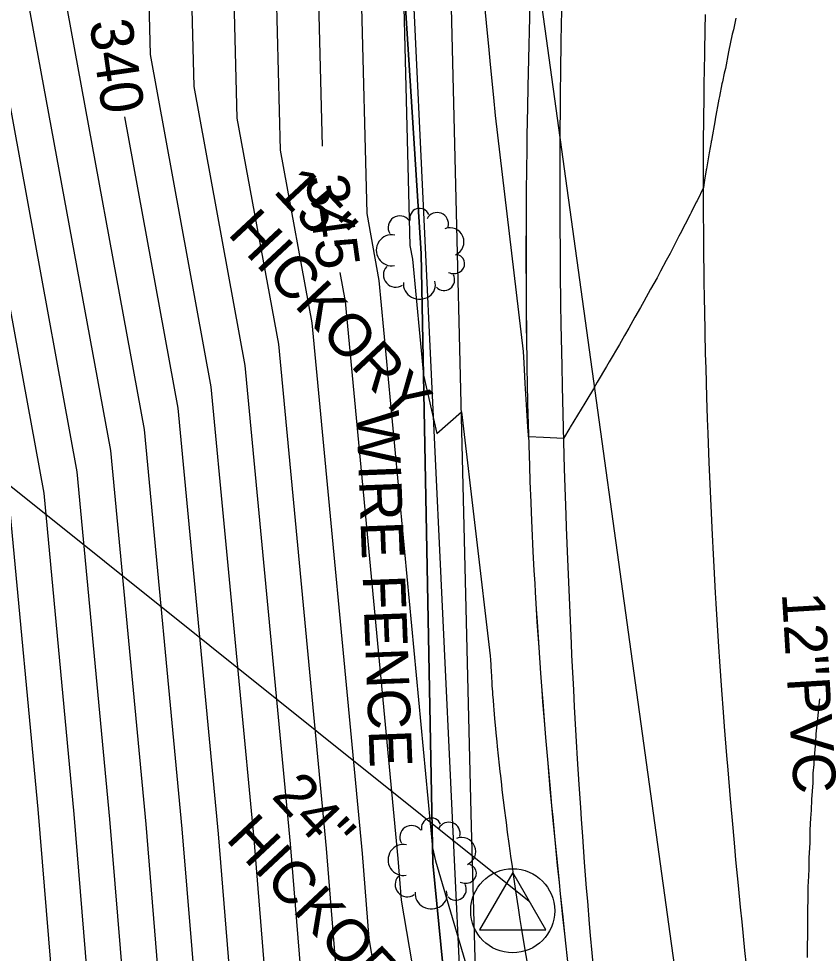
# Model space of a CAD drawing. Extents: x 487096 to 489566, y 221939 to 224454.
# Drawn here: x 488356.5 to 488416.7, y 222911.5 to 222981.8 of the extents above; entities that cross this region are included whole.
import ezdxf

# ---------------------------------------------------------------- set-up
doc = ezdxf.new("R2010")
doc.units = 0
for name, color, linetype in [('SV_BKLN_EARTH_TOP', 7, 'Continuous'), ('SV_CTRL_BM_INFO_BOX', 7, 'Continuous'), ('SV_CTRL_CGS', 7, 'Continuous'), ('SV_FENC_FENCES', 7, 'Continuous'), ('SV_FENC_FENCES_TX', 7, 'Continuous'), ('SV_MISC_MISC_TOPO', 7, 'Continuous'), ('SV_PIPE_PLAS_TX', 7, 'Continuous'), ('SV_ROAD_BITRD', 7, 'Continuous'), ('SV_ROWL_HWYLOC', 7, 'Continuous'), ('SV_SURF_INDEX_CONTOUR', 7, 'Continuous'), ('SV_SURF_INTER_CONTOUR', 7, 'Continuous'), ('SV_TRAF_PVMTL', 7, 'Continuous'), ('SV_TREE_TREEVEG', 7, 'Continuous'), ('SV_TREE_TREEVEG_TX', 7, 'Continuous'), ('SV_UTOH_OVERHEAD_LINES', 7, 'Continuous')]:
    doc.layers.add(name, color=color, linetype=linetype)

msp = doc.modelspace()

# ---------------------------------------------------------------- linework, layer by layer
at = {"layer": 'SV_BKLN_EARTH_TOP'}
msp.add_lwpolyline([(488391.814, 222875.894), (488390.567, 222921.008), (488388.639, 223000.073), (488389.407, 223042.325), (488396.478, 223078.484), (488405.528, 223123.261), (488407.475, 223152.677)], dxfattribs=at)
at = {"layer": 'SV_CTRL_BM_INFO_BOX'}
msp.add_line((488260.98, 223022.493), (488394.91, 222915.382), dxfattribs=at)
at = {"layer": 'SV_CTRL_CGS'}
msp.add_line((488393.66, 222914.66), (488393.66, 222914.66), dxfattribs=at)
msp.add_line((488393.66, 222914.66), (488393.66, 222914.66), dxfattribs=at)
msp.add_line((488393.66, 222914.66), (488393.66, 222914.66), dxfattribs=at)
msp.add_line((488393.66, 222914.66), (488393.66, 222914.66), dxfattribs=at)
msp.add_line((488393.66, 222914.66), (488393.66, 222914.66), dxfattribs=at)
msp.add_line((488393.66, 222914.66), (488393.66, 222914.66), dxfattribs=at)
msp.add_line((488393.66, 222914.66), (488393.66, 222914.66), dxfattribs=at)
msp.add_line((488393.66, 222914.66), (488393.66, 222914.66), dxfattribs=at)
msp.add_line((488393.66, 222914.66), (488393.66, 222914.66), dxfattribs=at)
msp.add_lwpolyline([(488393.66, 222917.548), (488391.159, 222913.217), (488396.161, 222913.217)], close=True, dxfattribs=at)
msp.add_lwpolyline([(488393.66, 222917.548), (488391.159, 222913.217), (488396.161, 222913.217)], close=True, dxfattribs=at)
msp.add_lwpolyline([(488393.66, 222917.548), (488391.159, 222913.217), (488396.161, 222913.217)], close=True, dxfattribs=at)
msp.add_lwpolyline([(488393.66, 222917.548), (488391.159, 222913.217), (488396.161, 222913.217)], close=True, dxfattribs=at)
msp.add_lwpolyline([(488393.66, 222917.548), (488391.159, 222913.217), (488396.161, 222913.217)], close=True, dxfattribs=at)
msp.add_lwpolyline([(488393.66, 222917.548), (488391.159, 222913.217), (488396.161, 222913.217)], close=True, dxfattribs=at)
msp.add_lwpolyline([(488393.66, 222917.548), (488391.159, 222913.217), (488396.161, 222913.217)], close=True, dxfattribs=at)
msp.add_lwpolyline([(488393.66, 222917.548), (488391.159, 222913.217), (488396.161, 222913.217)], close=True, dxfattribs=at)
msp.add_lwpolyline([(488393.66, 222917.548), (488391.159, 222913.217), (488396.161, 222913.217)], close=True, dxfattribs=at)
msp.add_circle((488393.66, 222914.66), 3.161, dxfattribs=at)
msp.add_circle((488393.66, 222914.66), 3.161, dxfattribs=at)
msp.add_circle((488393.66, 222914.66), 3.161, dxfattribs=at)
msp.add_circle((488393.66, 222914.66), 3.161, dxfattribs=at)
msp.add_circle((488393.66, 222914.66), 3.161, dxfattribs=at)
msp.add_circle((488393.66, 222914.66), 3.161, dxfattribs=at)
msp.add_circle((488393.66, 222914.66), 3.161, dxfattribs=at)
msp.add_circle((488393.66, 222914.66), 3.161, dxfattribs=at)
msp.add_circle((488393.66, 222914.66), 3.161, dxfattribs=at)
at = {"layer": 'SV_FENC_FENCES'}
msp.add_lwpolyline([(488400.559, 222861.835), (488391.815, 222875.913), (488387.651, 222918.235), (488386.769, 222964.099), (488384.515, 222999.563), (488389.407, 223042.325), (488396.478, 223078.484), (488402.804, 223123.48), (488407.475, 223152.677), (488415.007, 223209.78), (488415.388, 223241.145)], dxfattribs=at)
at = {"layer": 'SV_MISC_MISC_TOPO'}
msp.add_line((488393.659, 222914.659), (488393.659, 222914.659), dxfattribs=at)
at = {"layer": 'SV_ROAD_BITRD'}
for points in [[(488394.95, 222982.911), (488394.894, 222980.827), (488394.868, 222979.784), (488394.819, 222977.7), (488394.797, 222976.657), (488394.767, 222975.094), (488394.732, 222973.009), (488394.717, 222971.967), (488394.698, 222970.404), (488394.682, 222968.84), (488394.676, 222968.058), (488394.664, 222965.974), (488394.661, 222964.932), (488394.661, 222963.369), (488394.665, 222961.806), (488394.668, 222961.024), (488394.679, 222959.461), (488394.687, 222958.68), (488394.7, 222957.508), (488394.72, 222956.119), (488394.731, 222955.424), (488394.75, 222954.383), (488394.783, 222952.821), (488394.821, 222951.259), (488394.843, 222950.478), (488394.89, 222948.916), (488394.916, 222948.135), (488394.957, 222946.964), (488395.018, 222945.403), (488395.05, 222944.623), (488395.102, 222943.452), (488395.187, 222941.697), (488395.263, 222940.248), (488395.316, 222939.282), (488395.353, 222938.638), (488395.431, 222937.35), (488395.492, 222936.385), (488395.62, 222934.454), (488395.757, 222932.524), (488395.853, 222931.237), (488395.919, 222930.379), (488396.056, 222928.665), (488396.136, 222927.7), (488396.3, 222925.771), (488396.472, 222923.843), (488396.59, 222922.558), (488396.671, 222921.702), (488396.835, 222919.989), (488397.026, 222918.062), (488397.156, 222916.778), (488397.244, 222915.922), (488397.423, 222914.21), (488397.56, 222912.927), (488397.84, 222910.36)], [(488394.951, 222982.911), (488394.895, 222980.827), (488394.869, 222979.784), (488394.82, 222977.7), (488394.799, 222976.658), (488394.768, 222975.094), (488394.734, 222973.01), (488394.719, 222971.967), (488394.699, 222970.404), (488394.684, 222968.84), (488394.678, 222968.059), (488394.666, 222965.974), (488394.664, 222964.932), (488394.663, 222963.369), (488394.667, 222961.806), (488394.671, 222961.024), (488394.682, 222959.462), (488394.689, 222958.68), (488394.702, 222957.508), (488394.722, 222956.119), (488394.733, 222955.425), (488394.752, 222954.383), (488394.785, 222952.821), (488394.823, 222951.259), (488394.845, 222950.478), (488394.891, 222948.916), (488394.917, 222948.136), (488394.958, 222946.965), (488395.018, 222945.403), (488395.051, 222944.623), (488395.102, 222943.452), (488395.187, 222941.697), (488395.262, 222940.248), (488395.316, 222939.282), (488395.353, 222938.638), (488395.43, 222937.35), (488395.49, 222936.385), (488395.618, 222934.454), (488395.754, 222932.523), (488395.85, 222931.237), (488395.915, 222930.379), (488396.052, 222928.664), (488396.131, 222927.699), (488396.295, 222925.771), (488396.466, 222923.843), (488396.584, 222922.557), (488396.664, 222921.701), (488396.829, 222919.988), (488397.019, 222918.061), (488397.149, 222916.777), (488397.238, 222915.921), (488397.417, 222914.209), (488397.554, 222912.926), (488397.835, 222910.359)], [(488394.951, 222982.911), (488394.895, 222980.827), (488394.869, 222979.784), (488394.82, 222977.7), (488394.799, 222976.658), (488394.768, 222975.094), (488394.734, 222973.01), (488394.719, 222971.967), (488394.699, 222970.404), (488394.684, 222968.84), (488394.678, 222968.059), (488394.666, 222965.974), (488394.664, 222964.932), (488394.663, 222963.369), (488394.667, 222961.806), (488394.671, 222961.024), (488394.682, 222959.462), (488394.689, 222958.68), (488394.702, 222957.508), (488394.722, 222956.119), (488394.733, 222955.425), (488394.752, 222954.383), (488394.785, 222952.821), (488394.823, 222951.259), (488394.845, 222950.478), (488394.891, 222948.916), (488394.917, 222948.136), (488394.958, 222946.965), (488395.018, 222945.403), (488395.051, 222944.623), (488395.102, 222943.452), (488395.187, 222941.697), (488395.262, 222940.248), (488395.316, 222939.282), (488395.353, 222938.638), (488395.43, 222937.35), (488395.49, 222936.385), (488395.618, 222934.454), (488395.754, 222932.523), (488395.85, 222931.237), (488395.915, 222930.379), (488396.052, 222928.664), (488396.131, 222927.699), (488396.295, 222925.771), (488396.466, 222923.843), (488396.584, 222922.557), (488396.664, 222921.701), (488396.829, 222919.988), (488397.019, 222918.061), (488397.149, 222916.777), (488397.238, 222915.921), (488397.417, 222914.209), (488397.554, 222912.926), (488397.835, 222910.359)]]:
    msp.add_lwpolyline(points, dxfattribs=at)
at = {"layer": 'SV_ROWL_HWYLOC'}
msp.add_lwpolyline([(488415.388, 223241.145), (488415.007, 223209.78), (488407.475, 223152.677), (488402.804, 223123.48), (488396.478, 223078.484), (488389.407, 223042.325), (488386.961, 223020.944), (488384.515, 222999.563), (488386.769, 222964.099), (488387.651, 222918.235), (488391.815, 222875.913), (488394, 222859.238), (488415.207, 222774.386)], dxfattribs=at)
at = {"layer": 'SV_SURF_INDEX_CONTOUR'}
for points in [[(488379.351, 222972.188), (488378.624, 223000.814), (488378.664, 223008.462), (488377.682, 223042.865), (488378.243, 223058.541)], [(488349.178, 222980.783), (488355.841, 222944.471), (488357.935, 222922.292), (488360.157, 222895.18)], [(488364.437, 222974.386), (488368.457, 222952.478), (488371.483, 222920.442), (488373.074, 222901.024), (488375.167, 222888.746)], [(488391.924, 222877.1), (488391.755, 222878.086), (488391.753, 222878.109), (488391.517, 222878.914), (488385.288, 222915.445), (488385.03, 222918.592), (488381.074, 222960.484), (488380.671, 222962.679)]]:
    msp.add_lwpolyline(points, dxfattribs=at)
at = {"layer": 'SV_SURF_INTER_CONTOUR'}
for points in [[(488330.362, 223253.848), (488333.719, 223206.864), (488336.408, 223199.126), (488339.342, 223176.141), (488341.304, 223168.886), (488341.3, 223168.777), (488341.297, 223168.703), (488341.254, 223167.912), (488342.109, 223162.381), (488351.687, 223120.879), (488344.088, 223092.286), (488344.066, 223086.717), (488348.882, 223046.653), (488349.877, 223039.173), (488349.711, 223006.955), (488350.116, 222991.025), (488358.364, 222946.073), (488360.645, 222921.922), (488363.302, 222889.487), (488365.53, 222876.424), (488366.64, 222870.732), (488367.437, 222866.835), (488368.962, 222859.132)], [(488372.119, 222858.013), (488370.811, 222864.614), (488369.835, 222869.39), (488368.475, 222876.365), (488365.745, 222892.371), (488363.354, 222921.552), (488360.887, 222947.674), (488353.372, 222988.633), (488352.924, 223006.273), (488353.107, 223041.947), (488352.698, 223045.029), (488348.943, 223076.261), (488347.531, 223089.211), (488348.287, 223091.807), (488355.921, 223120.534), (488348.771, 223151.516), (488346.419, 223166.724), (488346.539, 223168.899), (488346.547, 223169.1), (488346.559, 223169.401), (488341.163, 223189.349), (488339.561, 223201.893), (488338.094, 223206.116), (488336.262, 223231.758)], [(488384.744, 222853.534), (488384.309, 222855.733), (488382.615, 222864.021), (488380.254, 222876.127), (488375.517, 222903.908), (488374.192, 222920.072), (488370.98, 222954.079), (488366.396, 222979.065), (488365.774, 223003.544)], [(488368.987, 223002.861), (488369.652, 222976.673), (488373.504, 222955.68), (488376.902, 222919.702), (488377.959, 222906.792), (488383.199, 222876.068), (488385.81, 222862.679), (488387.683, 222853.512), (488387.901, 222852.415)], [(488372.199, 223002.179), (488372.908, 222974.281), (488376.027, 222957.282), (488379.611, 222919.332), (488380.402, 222909.677), (488386.143, 222876.008), (488389.005, 222861.336), (488391.053, 222851.316), (488391.058, 222851.3), (488391.061, 222851.295), (488391.069, 222851.269), (488391.073, 222851.259)], [(488375.412, 223001.496), (488376.164, 222971.889), (488378.55, 222958.883), (488382.32, 222918.962), (488382.845, 222912.561), (488389.088, 222875.949), (488392.2, 222859.994), (488392.938, 222856.383), (488394.511, 222851.739), (488395.558, 222850.018), (488395.793, 222849.216), (488396.036, 222848.395), (488396.287, 222847.555), (488396.547, 222846.693), (488396.815, 222845.811), (488397.093, 222844.906), (488397.379, 222843.979), (488397.676, 222843.027), (488397.983, 222842.051), (488398.301, 222841.048), (488398.629, 222840.019), (488398.969, 222838.962)], [(488381.837, 223000.132), (488382.676, 222967.106), (488383.597, 222962.086), (488387.628, 222919.4), (488387.853, 222918.427), (488390.928, 222907.928)], [(488375.275, 222856.893), (488374.185, 222862.394), (488373.03, 222868.047), (488371.419, 222876.305), (488368.188, 222895.256), (488366.064, 222921.182), (488363.411, 222949.275), (488356.628, 222986.241)], [(488385.401, 222985.627), (488385.932, 222964.714), (488386.12, 222963.687), (488386.945, 222954.956), (488387.962, 222950.561), (488389.806, 222952.199), (488391.971, 222933.849), (488391.986, 222933.543), (488392.005, 222933.173), (488392.016, 222932.985), (488392.032, 222932.7), (488392.058, 222932.264), (488392.087, 222931.818), (488392.102, 222931.591), (488392.135, 222931.13), (488392.152, 222930.895), (488392.179, 222930.538), (488392.217, 222930.052), (488392.237, 222929.805), (488392.268, 222929.429), (488392.319, 222928.854), (488392.363, 222928.367), (488392.394, 222928.037), (488392.415, 222927.815), (488392.459, 222927.365), (488392.493, 222927.023), (488392.565, 222926.326), (488392.642, 222925.612), (488392.695, 222925.127), (488392.732, 222924.8), (488392.809, 222924.135), (488392.854, 222923.756), (488392.947, 222922.985), (488393.045, 222922.198), (488393.113, 222921.663), (488393.16, 222921.302), (488393.256, 222920.57), (488393.369, 222919.729), (488393.448, 222919.158), (488393.502, 222918.772), (488393.613, 222917.988), (488393.699, 222917.388), (488393.88, 222916.157), (488394.073, 222914.88), (488394.209, 222914), (488394.303, 222913.4), (488394.499, 222912.162), (488397.166, 222896.64)], [(488359.884, 222983.849), (488365.934, 222950.877), (488368.773, 222920.812), (488370.631, 222898.14), (488374.364, 222876.246), (488376.225, 222866.705), (488377.56, 222860.173), (488378.431, 222855.773)], [(488410.444, 222981.802), (488410.274, 222980.943), (488410.168, 222980.602), (488409.911, 222979.267), (488409.672, 222978.012), (488409.566, 222977.664), (488409.448, 222977.028), (488409.402, 222976.879), (488409.227, 222975.906), (488409.169, 222975.719), (488408.906, 222974.221), (488408.891, 222974.173), (488408.62, 222972.599), (488408.6, 222972.533), (488408.586, 222972.486), (488408.452, 222971.687), (488408.253, 222970.486), (488408.23, 222970.41), (488408.106, 222969.624), (488408.02, 222969.075), (488407.535, 222968.072), (488407.472, 222967.963), (488407.091, 222967.191), (488407.007, 222967.046), (488406.271, 222965.579), (488406.168, 222965.402), (488405.507, 222964.099), (488405.199, 222963.576), (488404.781, 222962.767), (488404.526, 222962.274), (488404.021, 222961.427), (488403.535, 222960.503), (488403.292, 222960.042), (488402.849, 222959.307), (488402.414, 222958.492), (488402.073, 222957.93), (488401.708, 222957.253), (488400.917, 222955.953), (488400.723, 222955.598), (488400.017, 222954.436), (488399.736, 222953.928), (488399.234, 222953.107), (488399.092, 222952.852), (488397.983, 222951.033), (488397.954, 222950.981), (488397.481, 222950.2), (488395.991, 222950.256), (488394.848, 222950.301), (488394.838, 222950.445), (488394.796, 222951.076), (488394.716, 222952.315), (488394.643, 222953.528), (488394.597, 222954.321), (488394.569, 222954.843), (488394.515, 222955.872), (488394.473, 222956.725), (488392.378, 222974.479), (488392.242, 222975.845), (488391.999, 222978.312), (488391.889, 222979.429), (488391.692, 222981.463), (488391.519, 222983.268)], [(488415.858, 222911.141), (488415.853, 222911.695), (488415.858, 222912.117), (488415.869, 222912.693), (488415.863, 222913.76), (488415.87, 222914.053), (488415.869, 222914.567), (488415.906, 222915.714), (488415.906, 222916.457), (488415.94, 222917.253), (488415.968, 222917.803), (488415.972, 222918.635), (488416.038, 222919.769), (488416.041, 222920.164), (488416.047, 222920.74), (488416.107, 222921.619), (488416.153, 222922.228), (488416.165, 222923.029), (488416.269, 222924.28), (488416.284, 222925.014), (488416.344, 222925.654), (488416.352, 222926), (488416.486, 222927.33), (488416.503, 222927.959), (488416.658, 222929.345), (488416.668, 222929.626), (488416.784, 222930.591)]]:
    msp.add_lwpolyline(points, dxfattribs=at)
at = {"layer": 'SV_TRAF_PVMTL'}
for points in [[(488397.326, 222982.422), (488397.284, 222980.095), (488397.251, 222977.769), (488397.234, 222976.217), (488397.224, 222975.183), (488397.21, 222973.114), (488397.206, 222971.95), (488397.202, 222969.623), (488397.207, 222967.295), (488397.215, 222965.744), (488397.222, 222964.709), (488397.241, 222962.64), (488397.27, 222960.312), (488397.293, 222958.76), (488397.31, 222957.726), (488397.35, 222955.657), (488397.383, 222954.105), (488397.407, 222953.07), (488397.459, 222951.001), (488397.487, 222949.966), (488397.547, 222947.897), (488397.613, 222945.828), (488397.66, 222944.449), (488397.692, 222943.53), (488397.76, 222941.691), (488397.851, 222939.379), (488397.899, 222938.223), (488397.975, 222936.49), (488398.054, 222934.757), (488398.095, 222933.89), (488398.181, 222932.157), (488398.226, 222931.291), (488398.295, 222929.992), (488398.392, 222928.26), (488398.442, 222927.394), (488398.52, 222926.095), (488398.642, 222924.147), (488398.756, 222922.417), (488398.815, 222921.552), (488398.906, 222920.254), (488399.05, 222918.309), (488399.201, 222916.364), (488399.279, 222915.392), (488399.424, 222913.664), (488399.498, 222912.8), (488399.613, 222911.505), (488399.793, 222909.564)], [(488411.26, 222910.576), (488411.144, 222911.663), (488410.919, 222913.838), (488410.809, 222914.926), (488410.648, 222916.557), (488410.464, 222918.491), (488410.374, 222919.457), (488410.242, 222920.908), (488410.051, 222923.083), (488409.868, 222925.259), (488409.78, 222926.347), (488409.609, 222928.523), (488409.527, 222929.611), (488409.408, 222931.243), (488409.257, 222933.42), (488409.184, 222934.508), (488409.08, 222936.141), (488408.98, 222937.773), (488408.931, 222938.59), (488408.822, 222940.525), (488408.77, 222941.492), (488408.695, 222942.944), (488408.59, 222945.122), (488408.493, 222947.299), (488408.448, 222948.388), (488408.365, 222950.566), (488408.327, 222951.655), (488408.273, 222953.289), (488408.21, 222955.468), (488408.182, 222956.557), (488408.143, 222958.191), (488408.11, 222959.825), (488408.096, 222960.643), (488408.073, 222962.096), (488408.063, 222962.822), (488408.05, 222963.912), (488408.035, 222965.547), (488408.025, 222967.181), (488408.022, 222967.999), (488408.02, 222969.634), (488408.02, 222970.452), (488408.024, 222971.678), (488408.029, 222972.522), (488408.041, 222974.209), (488408.059, 222975.896), (488408.074, 222977.021), (488408.086, 222977.771), (488408.112, 222979.271), (488408.145, 222980.959), (488408.171, 222982.084)]]:
    msp.add_lwpolyline(points, dxfattribs=at)
at = {"layer": 'SV_TREE_TREEVEG'}
for p, q in [((488386.769, 222964.099), (488386.769, 222964.099)), ((488387.651, 222918.235), (488387.651, 222918.235))]:
    msp.add_line(p, q, dxfattribs=at)
msp.add_lwpolyline([(488469.572, 222626.729), (488414.357, 222775.799), (488391.306, 222875.646), (488384.757, 223013.776), (488396.275, 223079.007), (488413.65, 223210.141), (488414.482, 223247.549), (488427.956, 223341.619), (488424.883, 223443.612), (488411.442, 223499.763), (488395.395, 223528.757), (488373.339, 223524.504)], dxfattribs=at)
for centre, radius, start, end in [((488386.658, 222966.749), 0.75, 23.2911, 192.35792), ((488385.158, 222966.062), 0.874, 35.99331, 211.459), ((488387.973, 222966.335), 0.85, 345.53076, 152.70931), ((488388.934, 222964.98), 1.059, 294.18586, 111.10825), ((488384.569, 222964.345), 1.171, 79.3292, 279.98885), ((488384.852, 222962.495), 0.922, 137.01566, 304.55007), ((488387.54, 222920.886), 0.75, 23.2911, 192.35792), ((488386.039, 222920.198), 0.874, 35.99331, 211.459), ((488388.855, 222920.472), 0.85, 345.53076, 152.70931), ((488389.816, 222919.116), 1.059, 294.18586, 111.10825), ((488385.45, 222918.481), 1.171, 79.3292, 279.98885), ((488385.734, 222916.631), 0.922, 137.01566, 304.55007)]:
    msp.add_arc(centre, radius, start, end, dxfattribs=at)
for centre, major_axis, ratio, start_param, end_param in [((488389.224, 222963.332), (0.822, -0.013), 0.901056, 4.216583, 7.444153), ((488388.488, 222962.129), (0.08, -0.798), 0.999752, 5.391582, 8.241319), ((488386.64, 222961.763), (-1.196, 0.159), 0.902156, 0, 3.5401), ((488390.106, 222917.468), (0.822, -0.013), 0.901056, 4.216583, 7.444153), ((488389.37, 222916.266), (0.08, -0.798), 0.999752, 5.391582, 8.241319), ((488387.522, 222915.899), (-1.196, 0.159), 0.902156, 0, 3.5401)]:
    msp.add_ellipse(centre, major_axis=major_axis, ratio=ratio, start_param=start_param, end_param=end_param, dxfattribs=at)
at = {"layer": 'SV_UTOH_OVERHEAD_LINES'}
msp.add_lwpolyline([(488477.012, 222631.438), (488424.125, 222778.25), (488391.68, 223012.955), (488449.873, 223205.72), (488469.995, 223438.334), (488349.561, 223622.886), (488159.178, 223693.118), (487993.175, 223755.783), (487804.196, 223830.216), (487742.262, 223860.212)], dxfattribs=at)

# ---------------------------------------------------------------- texts
at = {"layer": 'SV_FENC_FENCES_TX'}
msp.add_text('WIRE FENCE', height=3.2, rotation=272.20807, dxfattribs=at).set_placement((488381.889, 222952.232))
at = {"layer": 'SV_PIPE_PLAS_TX'}
msp.add_text("12''PVC", height=3.2, rotation=273.48787, dxfattribs=at).set_placement((488413.916, 222938.554))
at = {"layer": 'SV_SURF_INDEX_CONTOUR'}
for s, rotation, p in [('340', 278.14458, (488361.797, 222981.535)), ('345', 277.90478, (488378.061, 222969.839))]:
    msp.add_text(s, height=3.2, rotation=rotation, dxfattribs=at).set_placement(p)
at = {"layer": 'SV_TREE_TREEVEG_TX'}
for s, p in [('15"', (488375.567, 222968.763)), ('HICKORY', (488372.132, 222965.556)), ('24"', (488375.43, 222923.229)), ('HICKORY', (488371.995, 222920.021))]:
    msp.add_text(s, height=3.2, rotation=313.03859, dxfattribs=at).set_placement(p)

doc.saveas('drawing.dxf')
